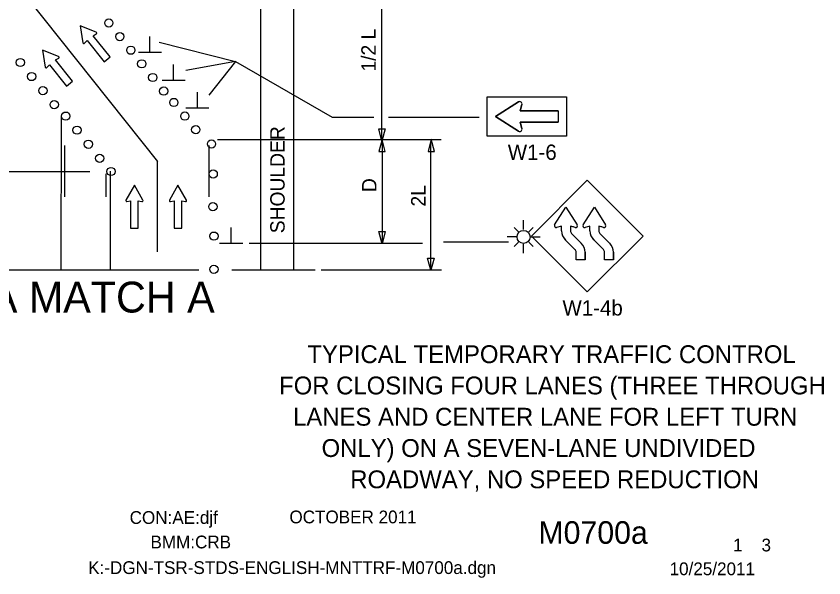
# Model space of a CAD drawing. Extents: x 16038 to 19504, y 5920 to 8321.
# Drawn here: x 17035.6 to 17427.9, y 7218.1 to 7491.1 of the extents above; entities that cross this region are included whole.
import ezdxf

# ---------------------------------------------------------------- set-up
doc = ezdxf.new("R2010")
doc.units = 0
for name, color, linetype in [('ALI_LEGAL_EX', 7, 'Continuous'), ('BORDER', 7, 'Continuous'), ('BORDER_SIGNAL_WO', 7, 'Continuous'), ('MT_SCRATCH_LEVEL_E', 7, 'Continuous'), ('PAVT_EDGE_EX', 7, 'Continuous'), ('TRAFFIC_SIGNS_PR', 7, 'Continuous'), ('TYPICAL_TEXT_DIMEN_PR', 7, 'Continuous')]:
    doc.layers.add(name, color=color, linetype=linetype)

msp = doc.modelspace()

# ---------------------------------------------------------------- linework, layer by layer
at = {"layer": 'ALI_LEGAL_EX'}
for points in [[(17059.25, 7403.26), (17059.25, 7428.26)], [(17129.25, 7403.26), (17129.25, 7428.26)], [(17104.19, 7376.61), (17104.15, 7420.48)], [(17079.25, 7403.26), (17079.25, 7414.37)]]:
    msp.add_lwpolyline(points, dxfattribs=at)
at = {"layer": 'BORDER'}
msp.add_line((17289.25, 7291.25), (17289.25, 7291.25), dxfattribs=at)
at = {"layer": 'MT_SCRATCH_LEVEL_E'}
for p, q in [((17066.68, 7486.33), (17068.02, 7478.11)), ((17074.45, 7483.29), (17066.68, 7486.33)), ((17066.68, 7486.33), (17068.02, 7478.11)), ((17074.45, 7483.29), (17066.68, 7486.33)), ((17072.93, 7481.59), (17074.51, 7482.46)), ((17072.93, 7481.59), (17074.51, 7482.46)), ((17081.24, 7471.26), (17072.93, 7481.59)), ((17081.24, 7471.26), (17072.93, 7481.59)), ((17068.83, 7477.88), (17070.01, 7479.24)), ((17068.83, 7477.88), (17070.01, 7479.24)), ((17070.01, 7479.24), (17078.33, 7468.91)), ((17070.01, 7479.24), (17078.33, 7468.91)), ((17048.4, 7474.52), (17049.74, 7466.31)), ((17056.17, 7471.48), (17048.4, 7474.52)), ((17048.4, 7474.52), (17049.74, 7466.31)), ((17056.17, 7471.48), (17048.4, 7474.52)), ((17054.64, 7469.78), (17056.22, 7470.65)), ((17054.64, 7469.78), (17056.22, 7470.65)), ((17062.96, 7459.45), (17054.64, 7469.78)), ((17062.96, 7459.45), (17054.64, 7469.78)), ((17078.33, 7468.91), (17081.24, 7471.26)), ((17078.33, 7468.91), (17081.24, 7471.26)), ((17050.54, 7466.07), (17051.73, 7467.44)), ((17050.54, 7466.07), (17051.73, 7467.44)), ((17051.73, 7467.44), (17060.04, 7457.11)), ((17051.73, 7467.44), (17060.04, 7457.11)), ((17060.04, 7457.11), (17062.96, 7459.45)), ((17060.04, 7457.11), (17062.96, 7459.45)), ((17093.01, 7408.96), (17088.9, 7401.72)), ((17093.01, 7408.96), (17088.9, 7401.72)), ((17097.16, 7401.72), (17093.01, 7408.96)), ((17097.16, 7401.72), (17093.01, 7408.96)), ((17114.15, 7408.96), (17110.04, 7401.72)), ((17114.15, 7408.96), (17110.04, 7401.72)), ((17118.3, 7401.72), (17114.15, 7408.96)), ((17118.3, 7401.72), (17114.15, 7408.96)), ((17089.38, 7401.03), (17091.16, 7401.35)), ((17089.38, 7401.03), (17091.16, 7401.35)), ((17091.16, 7401.35), (17091.16, 7388.09)), ((17091.16, 7401.35), (17091.16, 7388.09)), ((17094.9, 7388.09), (17094.9, 7401.35)), ((17094.9, 7401.35), (17096.68, 7401.03)), ((17094.9, 7388.09), (17094.9, 7401.35)), ((17094.9, 7401.35), (17096.68, 7401.03)), ((17110.52, 7401.03), (17112.3, 7401.35)), ((17110.52, 7401.03), (17112.3, 7401.35)), ((17112.3, 7401.35), (17112.3, 7388.09)), ((17112.3, 7401.35), (17112.3, 7388.09)), ((17116.04, 7388.09), (17116.04, 7401.35)), ((17116.04, 7401.35), (17117.82, 7401.03)), ((17116.04, 7388.09), (17116.04, 7401.35)), ((17116.04, 7401.35), (17117.82, 7401.03)), ((17091.16, 7388.09), (17094.9, 7388.09)), ((17091.16, 7388.09), (17094.9, 7388.09)), ((17112.3, 7388.09), (17116.04, 7388.09)), ((17112.3, 7388.09), (17116.04, 7388.09))]:
    msp.add_line(p, q, dxfattribs=at)
for centre, start, end in [((17074.28, 7482.86), 298.877, 68.6139), ((17074.28, 7482.86), 298.877, 68.6139), ((17068.48, 7478.19), 189.2656, 318.8046), ((17068.48, 7478.19), 189.2656, 318.8046), ((17055.99, 7471.05), 298.877, 68.6139), ((17055.99, 7471.05), 298.877, 68.6139), ((17050.19, 7466.39), 189.2656, 318.8046), ((17050.19, 7466.39), 189.2656, 318.8046), ((17089.31, 7401.49), 150.4248, 279.9638), ((17089.31, 7401.49), 150.4248, 279.9638), ((17096.75, 7401.49), 260.0362, 29.7731), ((17096.75, 7401.49), 260.0362, 29.7731), ((17110.45, 7401.49), 150.4248, 279.9638), ((17110.45, 7401.49), 150.4248, 279.9638), ((17117.89, 7401.49), 260.0362, 29.7731), ((17117.89, 7401.49), 260.0362, 29.7731)]:
    msp.add_arc(centre, 0.463, start, end, dxfattribs=at)
at = {"layer": 'PAVT_EDGE_EX'}
for p, q in [((17154.3, 8211.6), (17154.3, 7367.79)), ((17170.3, 8211.6), (17170.3, 7367.79)), ((17057.38, 7441.97), (17057.3, 7367.78)), ((17081.25, 7415.82), (17081.25, 7367.78))]:
    msp.add_line(p, q, dxfattribs=at)
at = {"layer": 'TRAFFIC_SIGNS_PR'}
for p, q in [((17279.56, 7449.38), (17268.4, 7442.28)), ((17280.4, 7445.08), (17281.24, 7448.14)), ((17268.4, 7442.28), (17279.56, 7435.18)), ((17298.8, 7445.08), (17280.4, 7445.08)), ((17298.8, 7445.08), (17298.8, 7439.48)), ((17281.24, 7436.42), (17280.4, 7439.48)), ((17280.4, 7439.48), (17298.8, 7439.48)), ((17285.81, 7384.19), (17312.96, 7411.34)), ((17312.96, 7411.34), (17340.11, 7384.19)), ((17282, 7387.37), (17282, 7391.87)), ((17279.49, 7386.33), (17277.38, 7388.43)), ((17284.51, 7386.33), (17286.62, 7388.43)), ((17278.85, 7383.81), (17274.01, 7383.81)), ((17285.15, 7383.81), (17290.04, 7383.81)), ((17312.96, 7357.03), (17285.81, 7384.19)), ((17310.03, 7380.72), (17305.32, 7385.43)), ((17305.32, 7385.43), (17310.03, 7380.72)), ((17340.11, 7384.19), (17312.96, 7357.03)), ((17323.83, 7380.72), (17319.11, 7385.43)), ((17319.11, 7385.43), (17323.83, 7380.72)), ((17279.49, 7381.3), (17277.38, 7379.19)), ((17282, 7375.85), (17282, 7380.26)), ((17284.51, 7381.3), (17286.62, 7379.19)), ((17306.98, 7377.67), (17302.27, 7382.38)), ((17306.98, 7377.67), (17302.27, 7382.38)), ((17320.78, 7377.67), (17316.06, 7382.38)), ((17320.77, 7377.67), (17316.06, 7382.38)), ((17307.58, 7372.6), (17307.58, 7376.3)), ((17311.9, 7372.6), (17311.9, 7376.3)), ((17321.38, 7372.6), (17321.38, 7376.3)), ((17325.69, 7372.6), (17325.69, 7376.3)), ((17311.9, 7372.6), (17307.58, 7372.6)), ((17325.69, 7372.6), (17321.38, 7372.6))]:
    msp.add_line(p, q, dxfattribs=at)
msp.add_lwpolyline([(17302.8, 7432.68), (17264.4, 7432.68), (17264.4, 7451.88), (17302.8, 7451.88)], close=True, dxfattribs=at)
for points in [[(17279.56, 7435.18), (17268.4, 7442.28), (17279.56, 7449.38)], [(17281.24, 7448.14), (17280.4, 7445.08), (17298.8, 7445.08), (17298.8, 7439.48), (17280.4, 7439.48), (17281.24, 7436.42)], [(17297.11, 7389.71), (17302.59, 7398.32), (17308.07, 7389.71)], [(17297.11, 7389.71), (17302.59, 7398.32), (17308.07, 7389.71)], [(17310.91, 7389.71), (17316.39, 7398.32), (17321.87, 7389.71)], [(17310.91, 7389.71), (17316.39, 7398.32), (17321.87, 7389.71)], [(17300.44, 7386.69), (17300.44, 7389.06), (17298.07, 7388.41)], [(17300.44, 7386.69), (17300.44, 7389.06), (17298.07, 7388.41)], [(17307.11, 7388.41), (17304.75, 7389.06), (17304.76, 7386.76)], [(17307.11, 7388.41), (17306.28, 7388.64), (17304.75, 7389.06), (17304.76, 7386.76)], [(17314.24, 7386.69), (17314.23, 7389.06), (17311.87, 7388.41)], [(17314.24, 7386.69), (17314.23, 7389.06), (17311.87, 7388.41)], [(17320.91, 7388.41), (17318.55, 7389.06), (17318.55, 7386.76)], [(17320.91, 7388.41), (17320.08, 7388.64), (17318.55, 7389.06), (17318.55, 7386.76)], [(17311.9, 7376.3), (17311.9, 7372.6), (17307.58, 7372.6), (17307.58, 7376.3)], [(17325.69, 7376.3), (17325.69, 7372.6), (17321.38, 7372.6), (17321.38, 7376.3)]]:
    msp.add_lwpolyline(points, dxfattribs=at)
for centre, radius in [((17080.58, 7487.78), 2), ((17085.92, 7481.15), 2), ((17091.25, 7474.53), 2), ((17037.57, 7468.56), 2), ((17096.58, 7467.91), 2), ((17043.07, 7461.73), 2), ((17101.92, 7461.28), 2), ((17048.57, 7454.9), 2), ((17107.25, 7454.66), 2), ((17054.07, 7448.07), 2), ((17112.15, 7449.14), 2), ((17059.66, 7442.5), 2), ((17117.48, 7442.51), 2), ((17122.81, 7435.89), 2), ((17065.16, 7435.67), 2), ((17070.66, 7428.84), 2), ((17130.43, 7428.95), 2), ((17076.16, 7422.01), 2), ((17081.63, 7415.6), 2), ((17131.28, 7414.38), 2), ((17131.13, 7398.49), 2), ((17282, 7383.81), 3.15), ((17131.63, 7384.18), 2), ((17131.63, 7368.05), 2)]:
    msp.add_circle(centre, radius, dxfattribs=at)
for centre, radius, start, end in [((17280.16, 7448.44), 1.12, 344.6731, 122.4696), ((17280.16, 7448.44), 1.12, 344.6731, 122.4696), ((17280.16, 7436.13), 1.12, 237.5304, 15.3269), ((17280.16, 7436.13), 1.12, 237.5304, 15.3269), ((17297.84, 7389.25), 0.866, 147.7292, 285.3172), ((17297.84, 7389.25), 0.866, 147.7196, 285.3201), ((17288, 7395.51), 10.8, 327.5335, 327.5431), ((17300.93, 7377.99), 10.8, 105.3192, 105.32), ((17306.61, 7386.76), 1.85, 180, 225.7875), ((17306.61, 7386.76), 1.85, 179.8762, 225.7877), ((17307.34, 7389.24), 0.864, 254.6014, 32.4796), ((17307.34, 7389.24), 0.866, 254.6148, 32.4712), ((17311.64, 7389.25), 0.866, 147.7292, 285.3172), ((17311.64, 7389.25), 0.866, 147.7196, 285.3201), ((17301.8, 7395.51), 10.8, 327.5335, 327.5431), ((17314.72, 7377.99), 10.8, 105.3192, 105.32), ((17320.4, 7386.76), 1.85, 180, 225.7875), ((17320.4, 7386.76), 1.85, 179.8762, 225.7877), ((17321.14, 7389.24), 0.864, 254.6014, 32.4796), ((17321.14, 7389.24), 0.866, 254.6148, 32.4712), ((17306.61, 7386.76), 6.17, 180.6181, 225.7875), ((17306.61, 7386.76), 6.17, 180.6245, 225.2313), ((17320.4, 7386.76), 6.17, 180.6181, 225.7875), ((17320.4, 7386.76), 6.17, 180.6245, 225.2313), ((17305.73, 7376.3), 6.17, 0, 45.7875), ((17305.73, 7376.3), 6.17, 0, 45.7875), ((17305.73, 7376.3), 6.17, 0, 45.7883), ((17319.53, 7376.3), 6.17, 0, 45.7875), ((17319.53, 7376.3), 6.17, 0, 45.7875), ((17319.53, 7376.3), 6.17, 0, 45.7883), ((17305.73, 7376.3), 1.85, 0, 47.628), ((17305.73, 7376.3), 1.85, 0, 45.7875), ((17319.53, 7376.3), 1.85, 0, 47.628), ((17319.53, 7376.3), 1.85, 0, 45.7875)]:
    msp.add_arc(centre, radius, start, end, dxfattribs=at)
at = {"layer": 'TYPICAL_TEXT_DIMEN_PR'}
for p, q in [((17213.25, 7430.79), (17213.25, 7516.27)), ((17035.77, 7506.44), (17104.15, 7420.48)), ((17100.56, 7473.44), (17100.56, 7481.23)), ((17104.99, 7478.44), (17142.15, 7469.03)), ((17106.19, 7473.44), (17094.94, 7473.44)), ((17112.05, 7459.82), (17112.05, 7467.61)), ((17142.15, 7469.03), (17117.98, 7464.69)), ((17142.15, 7469.03), (17129.16, 7452.76)), ((17142.15, 7469.03), (17189.05, 7441.98)), ((17117.67, 7459.82), (17106.42, 7459.82)), ((17123.58, 7446.37), (17123.58, 7454.16)), ((17129.21, 7446.37), (17117.96, 7446.37)), ((17189.05, 7441.98), (17209.26, 7441.98)), ((17216.47, 7441.98), (17260.45, 7441.98)), ((17213.25, 7430.38), (17211.68, 7436.24)), ((17211.68, 7436.24), (17213.25, 7436.24)), ((17213.25, 7436.24), (17214.82, 7436.24)), ((17214.82, 7436.24), (17213.25, 7430.38)), ((17242.07, 7430.93), (17133.44, 7430.9)), ((17213.3, 7431.1), (17211.73, 7425.24)), ((17214.87, 7425.24), (17213.3, 7431.1)), ((17213.4, 7430.27), (17213.4, 7381.08)), ((17237.17, 7431.24), (17235.6, 7425.37)), ((17236.94, 7367.99), (17236.94, 7429.91)), ((17238.74, 7425.37), (17237.17, 7431.24)), ((17211.73, 7425.24), (17213.3, 7425.24)), ((17213.3, 7425.24), (17214.87, 7425.24)), ((17235.6, 7425.37), (17237.17, 7425.37)), ((17237.17, 7425.37), (17238.74, 7425.37)), ((17071.39, 7415.43), (16994.67, 7415.41)), ((17140, 7380.59), (17140, 7388.37)), ((17213.29, 7380.5), (17211.72, 7386.36)), ((17211.72, 7386.36), (17213.29, 7386.36)), ((17213.29, 7386.36), (17214.86, 7386.36)), ((17214.86, 7386.36), (17213.29, 7380.5)), ((17145.62, 7380.59), (17134.37, 7380.59)), ((17232.88, 7380.53), (17148.71, 7380.51)), ((17243.08, 7381.4), (17274.69, 7381.4)), ((17237, 7367.65), (17235.43, 7373.51)), ((17235.43, 7373.51), (17237, 7373.51)), ((17237, 7373.51), (17238.57, 7373.51)), ((17238.57, 7373.51), (17237, 7367.65)), ((16960.07, 7367.78), (17124.22, 7367.78)), ((17140.3, 7367.78), (17180.83, 7367.78)), ((17242.08, 7367.65), (17183.65, 7367.63))]:
    msp.add_line(p, q, dxfattribs=at)

# ---------------------------------------------------------------- texts
at = {"layer": 'BORDER'}
for s, p in [('TYPICAL TEMPORARY TRAFFIC CONTROL', (17177.02, 7322.45)), ('FOR CLOSING FOUR LANES (THREE THROUGH', (17163.29, 7307.25)), ('LANES AND CENTER LANE FOR LEFT TURN', (17170.07, 7292.05)), ('ONLY) ON A SEVEN-LANE UNDIVIDED', (17183.91, 7276.85)), ('ROADWAY, NO SPEED REDUCTION', (17197.83, 7261.64))]:
    msp.add_text(s, height=8.6739, dxfattribs=at).set_placement(p)
at = {"layer": 'BORDER_SIGNAL_WO'}
for s, height, p in [('CON:AE:djf', 6.2, (17090.69, 7244.31)), ('    OCTOBER 2011    ', 6.2, (17159.08, 7244.59)), ('    M0700a   ', 11, (17272.86, 7234.63)), ('BMM:CRB   ', 6.2, (17100.81, 7232.42)), (' 1    3 ', 6.2, (17381.45, 7230.95)), ('K:-DGN-TSR-STDS-ENGLISH-MNTTRF-M0700a.dgn        ', 6.2, (17070.55, 7219.96)), ('10/25/2011    ', 6.2, (17352.93, 7219.38))]:
    msp.add_text(s, height=height, dxfattribs=at).set_placement(p)
at = {"layer": 'TRAFFIC_SIGNS_PR'}
for s, p in [('W1-6', (17274.34, 7421.24)), ('W1-4b', (17300.91, 7345.59))]:
    msp.add_text(s, height=7.44, dxfattribs=at).set_placement(p)
at = {"layer": 'TYPICAL_TEXT_DIMEN_PR'}
for s, p in [('1/2 L', (17210.22, 7464.16)), ('SHOULDER', (17165.98, 7385.57)), ('D', (17210.56, 7405.57)), ('2L', (17234.4, 7398.54))]:
    msp.add_text(s, height=7, rotation=90, dxfattribs=at).set_placement(p)
msp.add_text('A MATCH A', height=15, dxfattribs=at).set_placement((17022.78, 7347.05))

doc.saveas('drawing.dxf')
